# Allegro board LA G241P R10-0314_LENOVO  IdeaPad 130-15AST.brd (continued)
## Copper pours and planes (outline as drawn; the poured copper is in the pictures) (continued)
SPK_L1- on BOTTOM (solid shape): 9.81,22.69 9.81,21.87 9.83,21.85 9.83,21.4 9.98,21.25 9.98,20.45 9.87,20.34 9.65,20.34 9.55,20.44 9.55,21.65 9.59,21.68 9.59,22.7 9.64,22.75 9.74,22.75
SPK_L1- on IN1 (solid shape): 40.73,12.51 40.73,11.84 39.72,11.84 39.72,11.97 39.52,12.16 38.89,12.16 38.76,12.29 38.76,13.36 38.87,13.46 39.78,13.46
SPK_L1- on IN1 (solid shape): 9.98,21.38 9.98,19.27 9.73,19.02 9.73,18.59 8.71,18.59 8.71,19.12 9.48,19.88 9.48,21.4 9.53,21.46 9.91,21.46
SPK_L1-_CONN on TOP (solid shape): 42.29,9.03 42.29,8.82 42.17,8.69 42.17,8.63 42.12,8.59 42.12,6.8 41.97,6.65 41.27,6.65 41.11,6.8 41.11,8.98 41.27,9.14 42.19,9.14
SPK_L1-_CONN on TOP (solid shape): 42.4,12.9 43.47,12.9 43.57,12.8 43.57,11.86 43.53,11.82 42.79,11.82 42.76,11.84 41.94,11.84 41.94,11.84 41.64,11.84 41.56,11.92 40.77,11.92 40.77,13.37 40.77,13.71 40.8,13.74 41.56,13.74
SPK_L1-_CONN on IN1 (solid shape): 42.89,9.11 42.32,8.54 41.37,8.54 41.24,8.67 41.24,9.11 41.87,9.75 41.87,10.25 42.89,10.25
SPK_L1-_CONN on IN1 (solid shape): 43.59,12.78 43.59,11.9 43.46,11.78 43.08,11.78 42.89,11.59 41.95,11.59 41.87,11.67 41.87,12.22 42.55,12.9 43.47,12.9
SPK_L2+ on TOP (solid shape): 40.04,10.47 40.04,10.36 40.03,10.35 40.03,10.22 40.03,10.06 40.03,9.57 39.8,9.34 38.26,9.34 38.13,9.48 38.13,10 38.65,10.52 40,10.52
SPK_L2+ on BOTTOM (solid shape): 10.2,22.69 10.2,21.84 10.2,21.66 10.57,21.29 10.57,20.45 10.45,20.34 10.23,20.34 10.11,20.45 10.11,21.33 9.97,21.47 9.97,22.69 10.03,22.76 10.13,22.76
SPK_L2+ on IN1 (solid shape): 39.21,10 39.21,9.49 38.83,9.11 37.48,9.11 37.37,9.22 37.37,10.06 37.44,10.13 39.08,10.13
SPK_L2+ on IN1 (solid shape): 11.17,21.04 11.17,19.7 11.25,19.61 11.25,18.64 10.24,18.64 10.24,20.38 10.11,20.51 10.11,21.33 10.26,21.48 10.72,21.48
SPK_L2+_CONN on TOP (solid shape): 42.04,10.72 43.09,10.72 43.4,10.42 43.4,6.85 43.2,6.66 42.79,6.66 42.68,6.78 42.68,6.81 42.63,6.85 42.63,8.37 42.8,8.55 42.8,9.25 42.4,9.65 40.87,9.65 40.79,9.73 40.79,11.11 40.8,11.11 40.8,11.37 40.84,11.41 41.35,11.41
SPK_R1- on TOP (solid shape): 48.77,13.66 48.77,12.54 48.66,12.43 48.38,12.43 48.12,12.69 47.58,12.69 47.46,12.82 47.46,13.77 47.48,13.79 48.64,13.79
SPK_R1- on BOTTOM (solid shape): 9.41,22.71 9.41,21.36 9.4,21.35 9.4,20.43 9.31,20.35 8.97,20.35 8.9,20.42 8.9,21.29 9.14,21.54 9.14,21.54 9.17,21.57 9.17,22.69 9.26,22.77 9.34,22.77
SPK_R1- on IN1 (solid shape): 48.8,13.32 48.8,12.29 48.61,12.1 47.14,12.1 47.02,12.22 47.02,13.26 47.26,13.5 48.62,13.5
SPK_R1- on IN1 (solid shape): 9.32,21.35 9.32,20.01 8.21,18.89 8.21,18.81 7.19,18.81 7.19,19.27 8.08,20.16 8.56,20.16 8.77,20.36 8.77,21.35 8.84,21.43 9.25,21.43
SPK_R1-_CONN on TOP (solid shape): 46.73,13.7 46.73,11.91 45.88,11.91 45.87,11.91 44.42,11.91 44.33,11.82 43.96,11.82 43.84,11.93 43.84,12.8 43.96,12.92 44.98,12.92 45.86,13.8 46.63,13.8
SPK_R1-_CONN on TOP (solid shape): 44.83,9.07 44.83,8.78 44.67,8.62 44.67,6.81 44.52,6.67 44.08,6.67 43.91,6.84 43.91,8.36 43.74,8.53 43.74,8.88 43.74,8.88 43.74,9.05 43.89,9.2 44.7,9.2
SPK_R1-_CONN on IN1 (solid shape): 45.68,9.56 44.67,8.54 43.91,8.54 43.72,8.73 43.72,9.05 44.67,10 44.67,10.06 45.68,10.06
SPK_R1-_CONN on IN1 (solid shape): 45.68,12.22 45.68,11.59 44.67,11.59 44.48,11.78 43.97,11.78 43.84,11.9 43.84,12.8 43.96,12.92 44.99,12.92
SPK_R2+ on TOP (solid shape): 48.73,10.39 48.73,10 48.73,10 48.73,9.64 48.57,9.48 47.53,9.48 47.46,9.54 47.46,10.46 47.51,10.51 48.62,10.51
SPK_R2+ on BOTTOM (solid shape): 9.01,22.71 9.01,21.61 8.69,21.29 8.69,20.42 8.58,20.31 8.31,20.31 8.11,20.51 8.11,21.16 8.79,21.84 8.79,22.71 8.83,22.75 8.97,22.75
SPK_R2+ on IN1 (solid shape): 48.73,10.44 48.73,8.35 47.72,8.35 47.72,10.38 47.88,10.54 48.63,10.54
SPK_R2+ on IN1 (solid shape): 8.64,21.25 8.64,20.49 8.49,20.34 8,20.34 7.67,20.01 7.06,20.01 6.96,20.11 6.96,20.72 7.62,21.38 8.51,21.38
SPK_R2+_CONN on TOP (solid shape): 46.7,11.38 46.7,9.45 46.65,9.4 46.22,9.4 45.94,9.11 45.94,6.81 45.79,6.66 45.33,6.66 45.18,6.81 45.18,8.41 45.34,8.57 45.34,9.28 44.91,9.7 44.56,9.7 44.41,9.85 44.41,10.54 44.54,10.67 45.71,10.67 46.01,10.97 46.01,11.33 46.09,11.41 46.68,11.41
UG1_APU on BOTTOM (solid shape): 146.52,55.47 146.52,54.83 146.33,54.64 144.49,54.64 144.23,54.9 144.23,55.29 144.72,55.78 146.21,55.78
UG1_APU on BOTTOM (solid shape): 151.59,43.83 152.53,43.83 152.58,43.78 152.58,43.65 152.53,43.6 151.18,43.6 151.01,43.78 150.75,43.78 150.55,43.99 150.55,44.34 150.65,44.44 150.98,44.44
UG1_APU on IN2 (solid shape): 145.3,55.29 145.3,54.07 145.28,54.04 144.39,54.04 144.26,54.17 144.26,55.26 144.39,55.39 145.2,55.39
UG1_APU on IN2 (solid shape): 151.49,44.49 151.49,43.73 151.39,43.63 151.16,43.63 150.88,43.91 150.65,43.91 149.81,44.75 149.81,45.08 150.19,45.46 150.52,45.46
UG1_VGA on BOTTOM (solid shape): 63.72,110.77 63.72,109.89 63.53,109.69 62.26,109.69 61.75,110.2 61.75,110.9 61.88,111.03 63.46,111.03
UG1_VGA on BOTTOM (solid shape): 58.68,110.18 58.68,110 57.99,109.31 57.79,109.11 57.48,109.11 57.43,109.16 57.43,109.9 57.48,109.95 57.81,109.95 58.17,110.3 58.55,110.3
UG1_VGA on IN2 (solid shape): 59.39,109.92 58.68,109.92 58.14,109.39 57.89,109.39 57.74,109.54 57.74,110.51 58.17,110.94 59.39,110.94
UG1_VGA on IN2 (solid shape): 63.02,110.66 63.02,109.92 62.89,109.8 62.61,109.8 62.49,109.92 61.29,109.92 61.29,110.94 62.74,110.94
UG_CHG on BOTTOM (solid shape): 135,18.89 135,18.15 134.83,17.98 134.09,17.98 133.99,18.08 133.99,18.84 134.17,19.02 134.88,19.02
UG_CHG on BOTTOM (solid shape): 145.39,18.66 145.39,18.43 145.72,18.1 146.51,18.1 146.59,18.03 146.59,17.92 146.54,17.87 145.65,17.87 145.24,18.28 144.5,18.28 144.35,18.43 144.35,18.61 144.5,18.76 145.29,18.76
UG_CHG on IN2 (solid shape): 135.44,18.76 135.44,18.25 135.03,17.85 134.27,17.85 134.14,17.98 134.14,18.74 134.44,19.04 135.16,19.04
UG_CHG on IN2 (solid shape): 144.63,18.81 145.19,18.81 145.39,18.61 145.39,18.38 145.29,18.28 144.33,18.28 144.17,18.43 143.28,18.43 143.23,18.48 143.23,19.14 143.28,19.19 144.25,19.19
UG_DDR on TOP (solid shape): 36.98,105.12 36.98,104.36 36.79,104.17 36.16,104.17 35.97,104.36 35.97,105.12 36.1,105.25 36.86,105.25
UG_DDR on BOTTOM (solid shape): 37.09,113.56 37.09,112.77 37.29,112.57 37.57,112.57 37.87,112.26 37.87,111.9 37.77,111.8 37.42,111.8 36.88,112.34 36.88,113.56 36.93,113.61 37.04,113.61
UG_DDR on IN2 (solid shape): 38.76,111.35 38.76,110.84 37.81,110.84 37.75,110.9 37.75,111.16 36.86,112.04 36.86,112.49 37.05,112.68 37.43,112.68
UG_DDR on IN2 (solid shape): 37.75,105.19 37.75,104.74 37.18,104.17 36.1,104.17 35.97,104.3 35.97,105.12 36.1,105.25 36.86,105.25 37.05,105.44 37.49,105.44
UG_NB on BOTTOM (solid shape): 142.34,34.89 142.34,34.09 142.2,33.95 141.33,33.95 141.12,34.15 141.12,34.79 141.34,35.01 142.22,35.01
UG_NB on BOTTOM (solid shape): 152.58,41.37 152.58,41.24 152.5,41.17 152.43,41.17 151.67,40.4 151.13,40.4 151.06,40.48 151.06,40.73 151.74,41.42 152.53,41.42
UG_NB on IN1 (solid shape): 142.98,34.97 142.98,34 142.93,33.95 141.89,33.95 141.76,34.08 141.76,34.87 141.89,34.99 142.95,34.99
UG_NB on IN1 (solid shape): 152.05,40.99 152.05,40.66 151.72,40.33 151.54,40.33 150.78,39.57 150.17,39.57 150.14,39.59 150.14,40.38 150.42,40.66 150.8,40.66 151.01,40.86 151.23,40.86 151.49,41.11 151.92,41.11
VGA_B+ on TOP (solid shape): 67.21,111.09 67.08,110.96 63.78,110.96 63.72,111.03 63.72,112.43 63.91,112.62 67.21,112.62
VGA_B+ on BOTTOM (solid shape): 67.53,113.19 67.53,108.87 67.34,108.68 63.34,108.68 63.34,109.12 63.97,109.12 64.23,109.38 64.23,110.77 63.72,111.28 63.72,113.63 67.08,113.63
VMB2 on BOTTOM (solid shape): 108.88,27.65 108.88,23.18 108.73,23.02 106.51,23.02 106.33,23.21 106.33,27.59 106.53,27.79 108.74,27.79
VREF_0.775VALW on BOTTOM (solid shape): 147.47,31.97 149.14,31.97 149.33,31.78 149.33,31.21 149.11,30.99 147.59,30.99 146.53,29.93 145.96,29.93 145.9,29.99 145.9,30.52 146.02,30.63 146.09,30.63 146.31,30.85 146.31,32.23 146.36,32.29 147.16,32.29
N14166749 on TOP (solid shape): 76.67,10.19 76.1,10.19 76.1,8.79 76.67,8.79 76.67,8.48 75.4,8.48 75.28,8.6 73.69,8.6 73.62,8.54 71.59,8.54 71.47,8.67 71.47,9.17 71.59,9.3 73.05,9.3 73.5,9.75 73.5,10.13 73.81,10.44 76.67,10.44
N17215273 on BOTTOM (solid shape): 146.56,16.05 146.56,15.94 146.51,15.89 145.7,15.89 145.29,15.49 144.43,15.49 144.17,15.23 143.26,15.23 142.95,14.93 142.95,14.19 142.93,14.17 141.96,14.17 141.94,14.19 141.94,15.82 141.99,15.87 144.02,15.87 144.1,15.94 144.73,15.94 144.88,16.1 146.51,16.1
N17215386 on BOTTOM (solid shape): 136.67,13.63 136.67,12.75 137.19,12.24 137.82,12.24 137.89,12.17 137.89,11.59 135.6,11.59 135.53,11.66 135.53,13.55 135.81,13.83 136.46,13.83
N17225535 on TOP (solid shape): 53.81,10.95 53.81,9.36 54,9.17 54,7.52 54.51,7.02 54.51,5.87 54.19,5.55 53.94,5.55 53.88,5.62 53.88,6 53.81,6.06 52.42,6.06 52.42,5.49 51.84,5.49 51.72,5.62 51.72,6.63 51.97,6.89 52.54,6.89 52.8,7.14 52.8,11.02 52.92,11.14 53.62,11.14
N24107515 on TOP (solid shape): 20.73,137.38 20.73,136.36 20.6,136.24 18.44,136.24 18.32,136.36 18.32,137.44 20.67,137.44
N25219617 on TOP (solid shape): 29.77,8.53 30.08,8.53 30.08,8.2 30.05,8.17 29.67,8.17 28.96,8.88 28.22,8.88 28.17,8.93 28.17,9.14 28.22,9.19 29.11,9.19
N72585933 on TOP (solid shape): 40.99,111.22 40.99,110.77 40.22,110.77 39.97,110.52 39.97,109.69 38.95,109.69 38.95,111.35 40.86,111.35
N110838109 on TOP (solid shape): 17.76,105.05 17.76,99.37 18.61,98.52 18.61,97.95 18.35,97.69 18.02,97.69 16.88,98.83 16.88,105 17,105.12 17.68,105.12

Small or netless copper shapes (teardrops, artwork), in the pictures only: 144 on TOP, 29 on BOTTOM, 1 on IN1

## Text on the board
Ref Des/Silkscreen Bottom: A | H15
User.Comments: LA-G241P | 2018-03-21 | 2019-03-21 | DLADD/DE | crazy
User.39: FIGURE | SIZE | 8.0 | 22.0 | 28.0 | 35.0 | 98.0 | 126.0 | 130.0 | 43.0 | 47.0 | 63.0 | 67.0 | 35.0x16.0 | 39.0x26.0 | 49.0x26.0 | 55.0x24.0 | 55.0x31.0 | 63.0x24.0 | 63.0x35.0 | 71.0x31.0 | 79.0x31.0 | 102.0x31.0 | 138.0x98.0 | DRILL CHART: TOP to BOTTOM | ALL UNITS ARE IN MILS | TOLERANCE | +3.0/-3.0 | +2.0/-2.0 | +0.0/-0.0 | PLATED | NON-PLATED | QTY | 4328 | 19 | 18 | 10 | 7 | 1 | 5 | 2 | 4
User.40: stack-up setting ok
